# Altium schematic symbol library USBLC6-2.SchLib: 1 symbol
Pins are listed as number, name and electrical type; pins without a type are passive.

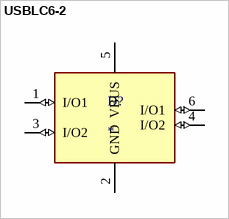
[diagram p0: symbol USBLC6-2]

## USBLC6-2
designator D?
17V Clamp 5A _8/20Âµs_ Ipp Tvs Diode Surface Mount SOT-23-6; MP: USBLC6-2SC6; MF: STMicroelectronics
footprint USBLC6-2-SOT666
footprint USBLC6-2-SOT236
pins: 1 I/O1 (io), 2 GND (power), 3 I/O2 (io), 4 I/O2 (io), 5 VBUS (power), 6 I/O1 (io)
